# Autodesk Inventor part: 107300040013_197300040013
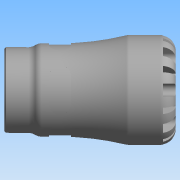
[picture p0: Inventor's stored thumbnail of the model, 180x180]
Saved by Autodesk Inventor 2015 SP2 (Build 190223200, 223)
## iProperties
Created: 2016-12
Part Number: 107300040013_197300040013
Material: Generic
Description: PLASSON FEMALE INTEGRAL BRASS THREAD 40X1.1/4" SERIES 1
Document SubType Name: Modeling
Designer: KIM
Density: 1 g/cm^3
Appearance: Default
Author: KIM
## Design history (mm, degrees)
derived "1073.ipt"
feature "Solid1::1073.ipt"
tag "TaggingFeature1"
body "Solid1"
other parameters: "d0" = 109, "d1" = 30.66, "d6" = 73, "d8" = 59.5, "d13" = 8, "d14" = 8, "d15" = 0, "d17" = 360 deg, "d19" = 8 deg, "d20" = 0.8, "d21" = 0.8, "d22" = 8 deg, "d24" = 0, "d26" = 360 deg, "d32" = 7, "d33" = 7, "d39" = 1.16856, "d42" = 38.952, "d43" = 54.6, "d46" = 3.33333, "d47" = 21, "d48" = 37.0044, "d50" = 4.95, "d51" = 0.7, "d54" = 14, "d55" = 8.8, "d57" = 15.68, "d58" = 0, "d68" = 360 deg, "d72" = 0.8, "d74" = 0, "d76" = 11.9, "H_" = 109, "l_" = 73, "G_" = 38.952, "l_2" = 21, "d9" = 10, "d49" = 15
